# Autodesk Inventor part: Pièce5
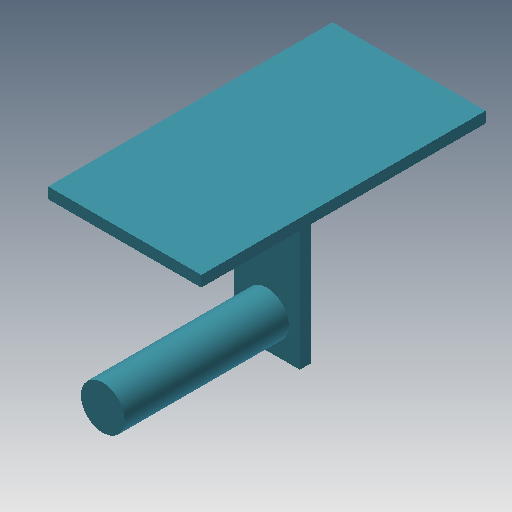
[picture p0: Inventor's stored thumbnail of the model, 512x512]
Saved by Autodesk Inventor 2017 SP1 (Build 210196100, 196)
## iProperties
Created: 2013-05
Part Number: Pièce5
Material: Générique
Document SubType Name: Modeling
Designer: jost thierry
Density: 1 g/cm^3
Mass: 0.642496 g
Surface Area: 12.065 cm^2
Volume: 0.642496 cm^3
Appearance: Vert turquoise
Author: jost thierry
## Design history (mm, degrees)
sketch "Esquisse1"
  geometry: C1 r 2 at (151.956, 69.491) reference; 1 further point
extrude "Extrusion1" new body sketch "Esquisse1" distance "d0" = 13; taper "d2" = 0 deg; dims "d1" = 3, "d3" = 0
sketch "Esquisse3"
  geometry: L1 (-3, 12)-(3, 12); L2 (3, 12)-(3, -3); L3 (3, -3)-(-3, -3); L4 (-3, -3)-(-3, 12); C1 r 2 at (0, 0) reference; 1 further point
  constraints: 8 end point, 2 parallel, 1 horizontal, 1 perpendicular
  dimensions: "d4" = 6 distance of L1.start L1.end; "d5" = 3 distance from line of L2 C1.centre (= 0.5 x d4); "d6" = 3 distance from line of L3 C1.centre (= d5); "d7" = 15 distance between parallel lines of L1 L3
extrude "Extrusion2" join sketch "Esquisse3" distance "d8" = 1; taper "d9" = 0 deg
sketch "Esquisse4"
  geometry: L1 (6, 0)-(0, 0) reference; L2 (-4, 12)-(10, 12); L3 (10, 12)-(10, -14); L4 (10, -14)-(-4, -14); L5 (-4, -14)-(-4, 12); 1 further point
  constraints: 8 end point, 2 parallel, 1 horizontal, 1 perpendicular
  dimensions: "d10" = 14 distance of L2.start L2.end; "d11" = 4 distance from line of L3 L1.start; "d12" = 26 distance between parallel lines of L4 L2; "d13" = 12 distance between parallel lines of L2 L1
extrude "Extrusion3" join sketch "Esquisse4" distance "d14" = 1; taper "d15" = 0 deg
node "Solide1"
node "Référence1"
